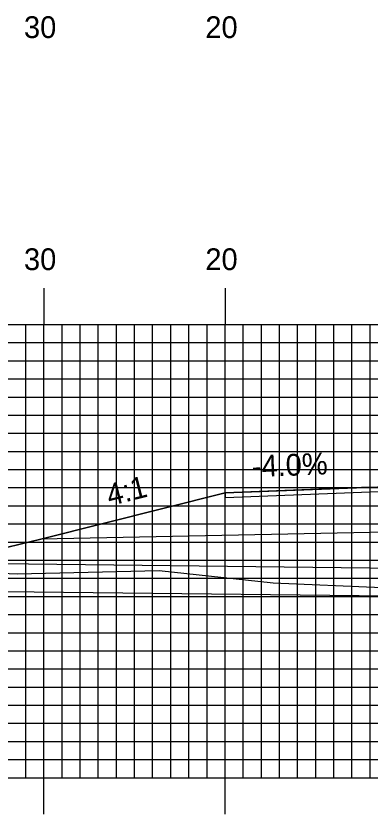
# Model space of a CAD drawing. Extents: x 1772022 to 1772366, y 442591 to 442811.
# Drawn here: x 1772156.55 to 1772176.09, y 442696.66 to 442740.68 of the extents above; entities that cross this region are included whole.
import ezdxf

# ---------------------------------------------------------------- set-up
doc = ezdxf.new("R2010")
doc.units = 0
for name, color, linetype in [('ANNOTATION', 7, 'Continuous'), ('D_Drainage_Culvert', 7, 'Continuous'), ('D_Roadway_Centerline', 7, 'Continuous'), ('D_Roadway_Edge_Shoulder', 7, 'Continuous'), ('D_Roadway_SlopeLines', 7, 'Continuous'), ('D_Roadway_SubGrade', 7, 'Continuous'), ('H_V ANNOTATION', 7, 'Continuous'), ('MAJOR', 7, 'Continuous'), ('MINOR', 7, 'Continuous'), ('S_Roadway_Centerline', 7, 'Continuous')]:
    doc.layers.add(name, color=color, linetype=linetype)

msp = doc.modelspace()

# ---------------------------------------------------------------- linework, layer by layer
at = {"layer": 'D_Drainage_Culvert'}
for points in [[(1772151.388, 442710.511), (1772149.389, 442710.534), (1772149.371, 442709.012), (1772229.366, 442708.104)], [(1772229.366, 442708.104), (1772229.383, 442709.604), (1772149.389, 442710.534)]]:
    msp.add_lwpolyline(points, dxfattribs=at)
at = {"layer": 'D_Roadway_Centerline'}
msp.add_lwpolyline([(1772156.094, 442711.374), (1772157.92, 442711.83), (1772158.274, 442711.919), (1772168.094, 442714.373), (1772175.815, 442714.682), (1772176.094, 442714.693), (1772176.512, 442714.702), (1772188.094, 442714.933), (1772188.512, 442714.925), (1772200.094, 442714.693), (1772207.815, 442714.385), (1772208.094, 442714.373), (1772217.913, 442711.918), (1772218.267, 442711.83), (1772218.796, 442711.698), (1772221.743, 442710.961)], dxfattribs=at)
at = {"layer": 'D_Roadway_Edge_Shoulder'}
msp.add_lwpolyline([(1772176.094, 442714.693), (1772168.094, 442714.373), (1772168.094, 442714.123), (1772176.094, 442714.443)], close=True, dxfattribs=at)
at = {"layer": 'D_Roadway_SlopeLines'}
msp.add_lwpolyline([(1772168.094, 442714.373), (1772157.92, 442711.83), (1772156.094, 442711.374)], dxfattribs=at)
at = {"layer": 'D_Roadway_SubGrade'}
msp.add_lwpolyline([(1772176.094, 442712.193), (1772157.92, 442711.83), (1772168.094, 442714.373), (1772168.094, 442714.123), (1772176.094, 442714.443), (1772188.094, 442714.683), (1772200.094, 442714.443), (1772208.094, 442714.123), (1772208.094, 442714.373), (1772218.267, 442711.83), (1772200.094, 442712.193), (1772188.094, 442712.433)], close=True, dxfattribs=at)
at = {"layer": 'MAJOR'}
for p, q in [((1772158.094, 442725.669), (1772158.094, 442723.665)), ((1772168.094, 442725.669), (1772168.094, 442723.665)), ((1772048.094, 442723.665), (1772328.094, 442723.665)), ((1772048.094, 442723.665), (1772328.094, 442723.665)), ((1772158.094, 442698.665), (1772158.094, 442723.665)), ((1772168.094, 442698.665), (1772168.094, 442723.665)), ((1772048.094, 442718.665), (1772328.094, 442718.665)), ((1772048.094, 442713.665), (1772328.094, 442713.665)), ((1772048.094, 442708.665), (1772328.094, 442708.665)), ((1772048.094, 442703.665), (1772328.094, 442703.665)), ((1772048.094, 442698.665), (1772328.094, 442698.665)), ((1772048.094, 442698.665), (1772328.094, 442698.665)), ((1772158.094, 442696.661), (1772158.094, 442698.665)), ((1772168.094, 442696.661), (1772168.094, 442698.665))]:
    msp.add_line(p, q, dxfattribs=at)
at = {"layer": 'MINOR'}
for p, q in [((1772157.094, 442698.665), (1772157.094, 442723.665)), ((1772159.094, 442698.665), (1772159.094, 442723.665)), ((1772160.094, 442698.665), (1772160.094, 442723.665)), ((1772161.094, 442698.665), (1772161.094, 442723.665)), ((1772162.094, 442698.665), (1772162.094, 442723.665)), ((1772163.094, 442698.665), (1772163.094, 442723.665)), ((1772164.094, 442698.665), (1772164.094, 442723.665)), ((1772165.094, 442698.665), (1772165.094, 442723.665)), ((1772166.094, 442698.665), (1772166.094, 442723.665)), ((1772167.094, 442698.665), (1772167.094, 442723.665)), ((1772169.094, 442698.665), (1772169.094, 442723.665)), ((1772170.094, 442698.665), (1772170.094, 442723.665)), ((1772171.094, 442698.665), (1772171.094, 442723.665)), ((1772172.094, 442698.665), (1772172.094, 442723.665)), ((1772173.094, 442698.665), (1772173.094, 442723.665)), ((1772174.094, 442698.665), (1772174.094, 442723.665)), ((1772175.094, 442698.665), (1772175.094, 442723.665)), ((1772176.094, 442698.665), (1772176.094, 442723.665)), ((1772048.094, 442722.665), (1772328.094, 442722.665)), ((1772048.094, 442721.665), (1772328.094, 442721.665)), ((1772048.094, 442720.665), (1772328.094, 442720.665)), ((1772048.094, 442719.665), (1772328.094, 442719.665)), ((1772048.094, 442717.665), (1772328.094, 442717.665)), ((1772048.094, 442716.665), (1772328.094, 442716.665)), ((1772048.094, 442715.665), (1772328.094, 442715.665)), ((1772048.094, 442714.665), (1772328.094, 442714.665)), ((1772048.094, 442712.665), (1772328.094, 442712.665)), ((1772048.094, 442711.665), (1772328.094, 442711.665)), ((1772048.094, 442710.665), (1772328.094, 442710.665)), ((1772048.094, 442709.665), (1772328.094, 442709.665)), ((1772048.094, 442707.665), (1772328.094, 442707.665)), ((1772048.094, 442706.665), (1772328.094, 442706.665)), ((1772048.094, 442705.665), (1772328.094, 442705.665)), ((1772048.094, 442704.665), (1772328.094, 442704.665)), ((1772048.094, 442702.665), (1772328.094, 442702.665)), ((1772048.094, 442701.665), (1772328.094, 442701.665)), ((1772048.094, 442700.665), (1772328.094, 442700.665)), ((1772048.094, 442699.665), (1772328.094, 442699.665))]:
    msp.add_line(p, q, dxfattribs=at)
at = {"layer": 'S_Roadway_Centerline'}
msp.add_lwpolyline([(1772128.852, 442711.962), (1772131.709, 442711.835), (1772148.852, 442710.265), (1772152.553, 442710.074), (1772156.608, 442709.92), (1772164.461, 442710.097), (1772170.743, 442709.418), (1772176.765, 442709.154), (1772184.09, 442709.072), (1772190.39, 442709.167), (1772199.456, 442709.084), (1772211.32, 442708.546), (1772211.609, 442708.541), (1772211.934, 442708.524), (1772231.881, 442708.062), (1772235.01, 442707.943), (1772238.683, 442707.821), (1772252.594, 442707.133)], dxfattribs=at)

# ---------------------------------------------------------------- texts
at = {"layer": 'ANNOTATION'}
for s, rotation, p in [('-4.0%', 2.2906, (1772169.586, 442715.235)), ('4:1', 14.0362, (1772161.72, 442713.642))]:
    msp.add_text(s, height=1.2, rotation=rotation, dxfattribs=at).set_placement(p)
at = {"layer": 'H_V ANNOTATION'}
for s, p in [('30', (1772156.991, 442739.465)), ('20', (1772167.002, 442739.465)), ('30', (1772156.991, 442726.665)), ('20', (1772167.002, 442726.665))]:
    msp.add_text(s, height=1.2, dxfattribs=at).set_placement(p)

doc.saveas('drawing.dxf')
